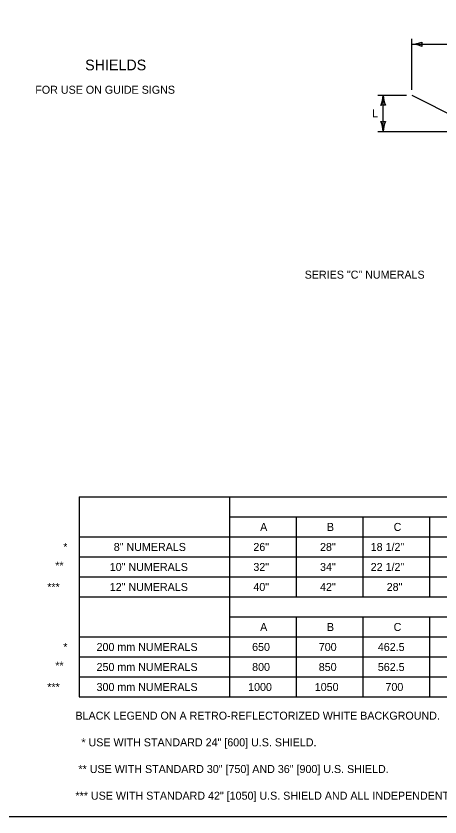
# Model space of a CAD drawing. Extents: x 49991.4 to 50021, y 49987.6 to 50011.4.
# Drawn here: x 50004.53 to 50007.71, y 49987.8 to 49993.8 of the extents above; entities that cross this region are included whole.
import ezdxf

# ---------------------------------------------------------------- set-up
doc = ezdxf.new("R2010")
doc.units = 0
for name, color, linetype in [('Level 1', 7, 'Continuous'), ('Level 2', 7, 'Continuous'), ('Level 3', 7, 'Continuous'), ('Level 4', 7, 'Continuous')]:
    doc.layers.add(name, color=color, linetype=linetype)

msp = doc.modelspace()

# ---------------------------------------------------------------- linework, layer by layer
at = {"layer": 'Level 1'}
msp.add_lwpolyline([(49999.3835, 49998.9992), (50016.7501, 49998.9992), (50016.7501, 49987.7988), (49999.3835, 49987.7988)], close=True, dxfattribs=at)
at = {"layer": 'Level 2'}
for p, q in [((50005.0051, 49990.1985), (50005.0051, 49989.4485)), ((50005.0051, 49990.1985), (50013.6326, 49990.1985)), ((50006.1326, 49990.1985), (50006.1326, 49989.4485)), ((50006.1326, 49990.0485), (50013.6326, 49990.0485)), ((50006.6326, 49990.0485), (50006.6326, 49989.4485)), ((50007.1326, 49990.0485), (50007.1326, 49989.4485)), ((50007.6326, 49990.0485), (50007.6326, 49989.4485)), ((50005.0051, 49989.8985), (50013.6326, 49989.8985)), ((50005.0051, 49989.7485), (50013.6326, 49989.7485)), ((50005.0051, 49989.5985), (50013.6326, 49989.5985)), ((50005.0051, 49989.4485), (50005.0051, 49988.6985)), ((50005.0051, 49989.4485), (50013.6326, 49989.4485)), ((50005.0051, 49989.4485), (50013.6326, 49989.4485)), ((50006.1326, 49989.4485), (50006.1326, 49988.6985)), ((50006.1326, 49989.2985), (50013.6326, 49989.2985)), ((50006.6326, 49989.2985), (50006.6326, 49988.6985)), ((50007.1326, 49989.2985), (50007.1326, 49988.6985)), ((50007.6326, 49989.2985), (50007.6326, 49988.6985)), ((50005.0051, 49989.1485), (50013.6326, 49989.1485)), ((50005.0051, 49988.9985), (50013.6326, 49988.9985)), ((50005.0051, 49988.8485), (50013.6326, 49988.8485)), ((50005.0051, 49988.6985), (50013.6326, 49988.6985))]:
    msp.add_line(p, q, dxfattribs=at)
at = {"layer": 'Level 3'}
for p, q in [((50007.5001, 49993.2508), (50007.5001, 49993.6324)), ((50007.5001, 49993.5924), (50009.0524, 49993.5924)), ((50007.2451, 49993.2108), (50007.4601, 49993.2108)), ((50007.2851, 49992.9383), (50007.2851, 49993.2108)), ((50007.2451, 49992.9383), (50007.8647, 49992.9383))]:
    msp.add_line(p, q, dxfattribs=at)
for centre, radius, start, end in [((50007.4886, 49993.8251), 0.233, 272.82731, 292.07716), ((50007.491, 49993.3702), 0.2223, 67.45601, 87.63952), ((50007.6283, 49993.5924), 0.0548, 162.13882, 197.86118), ((50007.063, 49993.2199), 0.2223, 337.45601, 357.63952), ((50007.5178, 49993.2223), 0.233, 182.82731, 202.07716), ((50007.2851, 49993.0826), 0.0548, 72.13882, 107.86118), ((50007.2851, 49993.0665), 0.0548, 252.13882, 287.86118), ((50007.0524, 49992.9268), 0.233, 2.82731, 22.07716), ((50007.5072, 49992.9291), 0.2223, 157.45601, 177.63952)]:
    msp.add_arc(centre, radius, start, end, dxfattribs=at)
at = {"layer": 'Level 4'}
msp.add_line((50007.5001, 49993.2108), (50009.986, 49991.9637), dxfattribs=at)

# ---------------------------------------------------------------- texts
at = {"layer": 'Level 2'}
for s, height, p in [('SHIELDS', 0.08, (50005.0507, 49993.3975)), ('FOR USE ON GUIDE SIGNS', 0.06, (50004.6768, 49993.2215)), ('L', 0.06, (50007.2027, 49993.0445)), ('SERIES "C" NUMERALS', 0.06, (50006.6969, 49991.8352)), ('A', 0.06, (50006.363, 49989.9435)), ('B', 0.06, (50006.8639, 49989.9435)), ('C', 0.06, (50007.3639, 49989.9435)), ('*', 0.06, (50004.8865, 49989.7935)), ('8" NUMERALS', 0.06, (50005.2653, 49989.7935)), ('26"', 0.06, (50006.3121, 49989.7935)), ('28"', 0.06, (50006.812, 49989.7935)), ('18 1/2"', 0.06, (50007.1919, 49989.7935)), ('**', 0.06, (50004.8265, 49989.654)), ('10" NUMERALS', 0.06, (50005.2353, 49989.6435)), ('32"', 0.06, (50006.3122, 49989.6435)), ('34"', 0.06, (50006.812, 49989.6435)), ('22 1/2"', 0.06, (50007.1919, 49989.6435)), ('***', 0.06, (50004.7665, 49989.4935)), ('12" NUMERALS', 0.06, (50005.2353, 49989.4935)), ('40"', 0.06, (50006.3122, 49989.4935)), ('42"', 0.06, (50006.812, 49989.4935)), ('28"', 0.06, (50007.312, 49989.4935)), ('A', 0.06, (50006.363, 49989.1935)), ('B', 0.06, (50006.8639, 49989.1935)), ('C', 0.06, (50007.3639, 49989.1935)), ('*', 0.06, (50004.8865, 49989.0435)), ('200 mm NUMERALS', 0.06, (50005.1363, 49989.0435)), ('650', 0.06, (50006.3027, 49989.0435)), ('700', 0.06, (50006.8026, 49989.0435)), ('462.5', 0.06, (50007.2455, 49989.0435)), ('**', 0.06, (50004.8265, 49988.904)), ('250 mm NUMERALS', 0.06, (50005.1363, 49988.8935)), ('800', 0.06, (50006.3028, 49988.8935)), ('850', 0.06, (50006.8026, 49988.8935)), ('562.5', 0.06, (50007.2455, 49988.8935)), ('***', 0.06, (50004.7665, 49988.7435)), ('300 mm NUMERALS', 0.06, (50005.1363, 49988.7435)), ('1000', 0.06, (50006.2728, 49988.7435)), ('1050', 0.06, (50006.7726, 49988.7435)), ('700', 0.06, (50007.3026, 49988.7435)), ('BLACK LEGEND ON A RETRO-REFLECTORIZED WHITE BACKGROUND.', 0.06, (50004.978, 49988.5284)), ('  * USE WITH STANDARD 24" [600] U.S. SHIELD.', 0.06, (50004.978, 49988.3284)), (' ** USE WITH STANDARD 30" [750] AND 36" [900] U.S. SHIELD.', 0.06, (50004.978, 49988.1284)), ('*** USE WITH STANDARD 42" [1050] U.S. SHIELD AND ALL INDEPENDENT USE.', 0.06, (50004.978, 49987.9284))]:
    msp.add_text(s, height=height, dxfattribs=at).set_placement(p)

doc.saveas('drawing.dxf')
